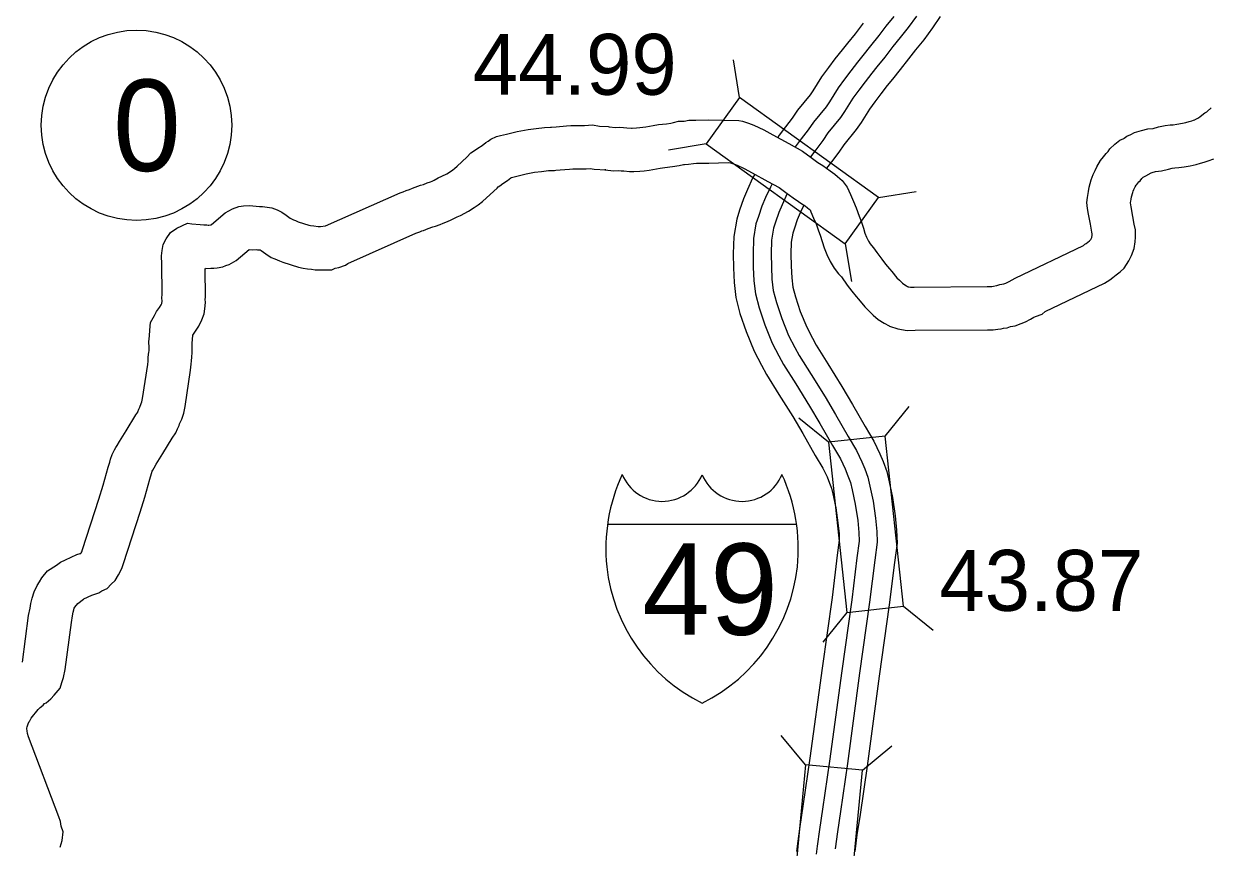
# Model space of a CAD drawing. Extents: x -939622 to -934245, y 1383184 to 1385301.
# Drawn here: x -936357.02 to -936332.35, y 1384807.78 to 1384824.91 of the extents above; entities that cross this region are included whole.
import ezdxf

# ---------------------------------------------------------------- set-up
doc = ezdxf.new("R2010")
doc.units = 0
for name, color, linetype in [('10', 7, 'Continuous'), ('19', 7, 'Continuous'), ('20', 7, 'Continuous'), ('21', 7, 'Continuous'), ('23', 7, 'Continuous'), ('25', 7, 'Continuous'), ('27', 7, 'Continuous')]:
    doc.layers.add(name, color=color, linetype=linetype)

msp = doc.modelspace()

# ---------------------------------------------------------------- linework, layer by layer
at = {"layer": '10'}
for points in [[(-936334.834, 1384820.419), (-936334.834, 1384820.42), (-936334.811, 1384820.463), (-936334.808, 1384820.509), (-936334.807, 1384820.538), (-936334.814, 1384820.572), (-936334.844, 1384820.738), (-936334.883, 1384820.948), (-936334.902, 1384821.064), (-936334.915, 1384821.19), (-936334.904, 1384821.297), (-936334.892, 1384821.375), (-936334.883, 1384821.42), (-936334.869, 1384821.507), (-936334.825, 1384821.66), (-936334.789, 1384821.773), (-936334.747, 1384821.855), (-936334.713, 1384821.931), (-936334.636, 1384822.062), (-936334.572, 1384822.143), (-936334.515, 1384822.208), (-936334.491, 1384822.236), (-936334.477, 1384822.252), (-936334.436, 1384822.307), (-936334.333, 1384822.403), (-936334.228, 1384822.487), (-936334.148, 1384822.526), (-936334.144, 1384822.528), (-936334.084, 1384822.573), (-936334.005, 1384822.605), (-936333.926, 1384822.65), (-936333.781, 1384822.688), (-936333.646, 1384822.721), (-936333.538, 1384822.734), (-936333.429, 1384822.763), (-936333.29, 1384822.792), (-936333.182, 1384822.805), (-936333.122, 1384822.81), (-936333.044, 1384822.824), (-936332.929, 1384822.843), (-936332.862, 1384822.856), (-936332.79, 1384822.878), (-936332.736, 1384822.891), (-936332.7, 1384822.904), (-936332.674, 1384822.913), (-936332.662, 1384822.921), (-936332.599, 1384822.956), (-936332.559, 1384822.982), (-936332.461, 1384823.054), (-936332.423, 1384823.076), (-936332.418, 1384823.081), (-936332.329, 1384823.161)], [(-936346.071, 1384822.758), (-936346.048, 1384822.758), (-936345.952, 1384822.768), (-936345.735, 1384822.786), (-936345.647, 1384822.79), (-936345.518, 1384822.795), (-936345.364, 1384822.794), (-936345.195, 1384822.808), (-936345.05, 1384822.779), (-936344.868, 1384822.769), (-936344.849, 1384822.767), (-936344.716, 1384822.754), (-936344.632, 1384822.755), (-936344.553, 1384822.749), (-936344.48, 1384822.746), (-936344.388, 1384822.737), (-936344.373, 1384822.737), (-936344.283, 1384822.743), (-936344.216, 1384822.749), (-936344.151, 1384822.756), (-936344.09, 1384822.768), (-936343.937, 1384822.791), (-936343.822, 1384822.812), (-936343.655, 1384822.829), (-936343.565, 1384822.844), (-936343.51, 1384822.856)], [(-936343.51, 1384822.856), (-936343.407, 1384822.883), (-936343.291, 1384822.885), (-936343.192, 1384822.904), (-936343.047, 1384822.905), (-936342.79, 1384822.908), (-936342.155, 1384822.899)], [(-936342.155, 1384822.899), (-936342.08, 1384822.88), (-936341.953, 1384822.839), (-936341.842, 1384822.799), (-936341.635, 1384822.702), (-936341.446, 1384822.598), (-936341.114, 1384822.418), (-936340.832, 1384822.261), (-936340.647, 1384822.128), (-936340.509, 1384822.026), (-936340.41, 1384821.959), (-936340.332, 1384821.905), (-936340.252, 1384821.85), (-936340.157, 1384821.779), (-936340.105, 1384821.733), (-936340.008, 1384821.65), (-936339.901, 1384821.508), (-936339.831, 1384821.359), (-936339.772, 1384821.214), (-936339.713, 1384821.079), (-936339.651, 1384820.908), (-936339.613, 1384820.803), (-936339.564, 1384820.655), (-936339.531, 1384820.55), (-936339.501, 1384820.472), (-936339.459, 1384820.388), (-936339.426, 1384820.331), (-936339.397, 1384820.295), (-936339.352, 1384820.246), (-936339.284, 1384820.153)], [(-936354.15, 1384819.908), (-936354.16, 1384820.084), (-936354.148, 1384820.196), (-936354.122, 1384820.317), (-936354.059, 1384820.438), (-936353.97, 1384820.57), (-936353.839, 1384820.66), (-936353.615, 1384820.761), (-936353.53, 1384820.749), (-936353.355, 1384820.736), (-936353.278, 1384820.73), (-936353.215, 1384820.724), (-936353.192, 1384820.721), (-936353.172, 1384820.722), (-936353.142, 1384820.724), (-936353.128, 1384820.725), (-936353.119, 1384820.731), (-936352.833, 1384820.975), (-936352.684, 1384821.057), (-936352.551, 1384821.108), (-936352.451, 1384821.119), (-936352.328, 1384821.128), (-936352.124, 1384821.109), (-936352.058, 1384821.11), (-936351.96, 1384821.095), (-936351.864, 1384821.079), (-936351.751, 1384821.036), (-936351.656, 1384820.989), (-936351.57, 1384820.928), (-936351.483, 1384820.868), (-936351.471, 1384820.859), (-936351.411, 1384820.83), (-936351.376, 1384820.818), (-936351.315, 1384820.791), (-936351.097, 1384820.721), (-936351.064, 1384820.715), (-936350.989, 1384820.703), (-936350.898, 1384820.692), (-936350.883, 1384820.689), (-936350.874, 1384820.689), (-936350.85, 1384820.689), (-936350.746, 1384820.704), (-936349.198, 1384821.392), (-936349.131, 1384821.414), (-936349.073, 1384821.442), (-936349.001, 1384821.463), (-936348.937, 1384821.488), (-936348.773, 1384821.55), (-936348.711, 1384821.563), (-936348.709, 1384821.564), (-936348.637, 1384821.598), (-936348.563, 1384821.622), (-936348.53, 1384821.636), (-936348.492, 1384821.656), (-936348.407, 1384821.703), (-936348.329, 1384821.737), (-936348.225, 1384821.791), (-936348.152, 1384821.838), (-936348.101, 1384821.872), (-936348.068, 1384821.898), (-936348.013, 1384821.949), (-936347.811, 1384822.137), (-936347.728, 1384822.222), (-936347.629, 1384822.284), (-936347.58, 1384822.32), (-936347.493, 1384822.378), (-936347.415, 1384822.439), (-936347.369, 1384822.468), (-936347.312, 1384822.509), (-936347.192, 1384822.562), (-936347.107, 1384822.584), (-936346.983, 1384822.616), (-936346.76, 1384822.667), (-936346.537, 1384822.71), (-936346.371, 1384822.728), (-936346.193, 1384822.753), (-936346.071, 1384822.758)], [(-936339.03, 1384818.624), (-936339.022, 1384818.619), (-936338.845, 1384818.564), (-936338.656, 1384818.526), (-936338.487, 1384818.532), (-936336.98, 1384818.541), (-936336.863, 1384818.543), (-936336.766, 1384818.554), (-936336.698, 1384818.566), (-936336.649, 1384818.575), (-936336.576, 1384818.586), (-936336.505, 1384818.609), (-936336.408, 1384818.627), (-936336.282, 1384818.674), (-936336.191, 1384818.71), (-936336.092, 1384818.763), (-936336.018, 1384818.806), (-936335.987, 1384818.821), (-936335.845, 1384818.87), (-936335.781, 1384818.923), (-936334.55, 1384819.512), (-936334.441, 1384819.582), (-936334.377, 1384819.63), (-936334.308, 1384819.685), (-936334.223, 1384819.75), (-936334.144, 1384819.827), (-936334.042, 1384819.979), (-936334.019, 1384820.035), (-936333.988, 1384820.092), (-936333.931, 1384820.236), (-936333.915, 1384820.371), (-936333.908, 1384820.469), (-936333.905, 1384820.62), (-936333.93, 1384820.742), (-936333.958, 1384820.899), (-936333.996, 1384821.103), (-936334.009, 1384821.183), (-936334.01, 1384821.189), (-936334.005, 1384821.221), (-936333.997, 1384821.26), (-936333.989, 1384821.311), (-936333.964, 1384821.399), (-936333.954, 1384821.43), (-936333.937, 1384821.463), (-936333.914, 1384821.514), (-936333.891, 1384821.552), (-936333.879, 1384821.568), (-936333.835, 1384821.618), (-936333.812, 1384821.645), (-936333.773, 1384821.689), (-936333.761, 1384821.706), (-936333.746, 1384821.72), (-936333.744, 1384821.721), (-936333.694, 1384821.746), (-936333.582, 1384821.81), (-936333.561, 1384821.816), (-936333.487, 1384821.833), (-936333.368, 1384821.847), (-936333.22, 1384821.887), (-936333.145, 1384821.903), (-936333.086, 1384821.91), (-936333.002, 1384821.918), (-936332.895, 1384821.936), (-936332.771, 1384821.957), (-936332.642, 1384821.982), (-936332.552, 1384822.01), (-936332.475, 1384822.028), (-936332.392, 1384822.058), (-936332.28, 1384822.099)], [(-936353.252, 1384819.822), (-936353.237, 1384819.821), (-936353.131, 1384819.822), (-936353.071, 1384819.827), (-936353.002, 1384819.832), (-936352.887, 1384819.854), (-936352.824, 1384819.878), (-936352.751, 1384819.898), (-936352.609, 1384819.983), (-936352.336, 1384820.215), (-936352.26, 1384820.203), (-936352.193, 1384820.211), (-936352.161, 1384820.208), (-936352.119, 1384820.209), (-936352.11, 1384820.208), (-936352.09, 1384820.193), (-936351.989, 1384820.123), (-936351.879, 1384820.05), (-936351.805, 1384820.021), (-936351.755, 1384819.997), (-936351.705, 1384819.98), (-936351.635, 1384819.948), (-936351.311, 1384819.845), (-936351.213, 1384819.828), (-936351.12, 1384819.812), (-936351.038, 1384819.802), (-936350.962, 1384819.788), (-936350.864, 1384819.789), (-936350.801, 1384819.79), (-936350.756, 1384819.79), (-936350.615, 1384819.792), (-936350.546, 1384819.825), (-936350.47, 1384819.841), (-936350.333, 1384819.889), (-936350.285, 1384819.924), (-936348.872, 1384820.552), (-936348.79, 1384820.579), (-936348.748, 1384820.6), (-936348.713, 1384820.61), (-936348.616, 1384820.647), (-936348.518, 1384820.684), (-936348.461, 1384820.696), (-936348.361, 1384820.733), (-936348.302, 1384820.761), (-936348.245, 1384820.78), (-936348.147, 1384820.821), (-936348.066, 1384820.863), (-936348.008, 1384820.895), (-936347.944, 1384820.923), (-936347.774, 1384821.011), (-936347.658, 1384821.086), (-936347.572, 1384821.143), (-936347.481, 1384821.215), (-936347.4, 1384821.291), (-936347.182, 1384821.492), (-936347.158, 1384821.517), (-936347.121, 1384821.54), (-936347.063, 1384821.583), (-936346.966, 1384821.648), (-936346.896, 1384821.702), (-936346.88, 1384821.712), (-936346.769, 1384821.742), (-936346.574, 1384821.786), (-936346.403, 1384821.819), (-936346.259, 1384821.835), (-936346.114, 1384821.856), (-936345.99, 1384821.86), (-936345.96, 1384821.863)], [(-936345.96, 1384821.863), (-936345.871, 1384821.871), (-936345.675, 1384821.888), (-936345.608, 1384821.891), (-936345.504, 1384821.895), (-936345.329, 1384821.894), (-936345.246, 1384821.901), (-936345.164, 1384821.885), (-936344.921, 1384821.87), (-936344.94, 1384821.872), (-936344.756, 1384821.853), (-936344.66, 1384821.854), (-936344.602, 1384821.85), (-936344.543, 1384821.848), (-936344.43, 1384821.836), (-936344.338, 1384821.837), (-936344.213, 1384821.846), (-936344.124, 1384821.853), (-936344.016, 1384821.866), (-936343.94, 1384821.88), (-936343.789, 1384821.903), (-936343.694, 1384821.92), (-936343.533, 1384821.937), (-936343.396, 1384821.96), (-936343.302, 1384821.98), (-936343.285, 1384821.985), (-936343.199, 1384821.986), (-936343.1, 1384822.005), (-936343.036, 1384822.006), (-936342.779, 1384822.009), (-936342.375, 1384822.026)], [(-936342.375, 1384822.026), (-936342.327, 1384822.014), (-936342.244, 1384821.987), (-936342.187, 1384821.967), (-936342.043, 1384821.899), (-936341.877, 1384821.808), (-936341.548, 1384821.629), (-936341.316, 1384821.501), (-936341.178, 1384821.401), (-936341.027, 1384821.29), (-936340.916, 1384821.215), (-936340.843, 1384821.165), (-936340.778, 1384821.12), (-936340.723, 1384821.078), (-936340.694, 1384821.053), (-936340.674, 1384821.036), (-936340.655, 1384820.996), (-936340.601, 1384820.864), (-936340.549, 1384820.745), (-936340.498, 1384820.602), (-936340.464, 1384820.51), (-936340.421, 1384820.378), (-936340.38, 1384820.25), (-936340.324, 1384820.107), (-936340.253, 1384819.964), (-936340.173, 1384819.824), (-936340.081, 1384819.708), (-936340.022, 1384819.645), (-936339.902, 1384819.474)], [(-936338.631, 1384819.44), (-936338.622, 1384819.437), (-936338.583, 1384819.429), (-936338.506, 1384819.432), (-936336.988, 1384819.441), (-936336.919, 1384819.442), (-936336.896, 1384819.445), (-936336.857, 1384819.452), (-936336.798, 1384819.462), (-936336.788, 1384819.464), (-936336.728, 1384819.484), (-936336.646, 1384819.499), (-936336.605, 1384819.514), (-936336.571, 1384819.527), (-936336.534, 1384819.547), (-936336.411, 1384819.62), (-936334.989, 1384820.299), (-936334.956, 1384820.321), (-936334.93, 1384820.34), (-936334.863, 1384820.394), (-936334.832, 1384820.418)], [(-936339.284, 1384820.153), (-936339.181, 1384820.013), (-936339.102, 1384819.91), (-936339.018, 1384819.811), (-936338.971, 1384819.753), (-936338.867, 1384819.627), (-936338.814, 1384819.573), (-936338.752, 1384819.515), (-936338.723, 1384819.489), (-936338.669, 1384819.457), (-936338.65, 1384819.446), (-936338.631, 1384819.44)], [(-936357.047, 1384811.625), (-936356.922, 1384812.598), (-936356.892, 1384812.755), (-936356.877, 1384812.846), (-936356.85, 1384812.96), (-936356.808, 1384813.091), (-936356.744, 1384813.22), (-936356.696, 1384813.299), (-936356.646, 1384813.381), (-936356.53, 1384813.528), (-936356.344, 1384813.643), (-936356.262, 1384813.708), (-936356.157, 1384813.759), (-936355.919, 1384813.867), (-936355.852, 1384813.887), (-936355.838, 1384813.892), (-936355.829, 1384813.901), (-936355.817, 1384813.926), (-936355.801, 1384813.97), (-936355.459, 1384815.019), (-936355.37, 1384815.313), (-936355.266, 1384815.687), (-936355.234, 1384815.791), (-936355.219, 1384815.853), (-936355.188, 1384815.95), (-936355.137, 1384816.049), (-936355.108, 1384816.095), (-936355.084, 1384816.136), (-936355.034, 1384816.216), (-936354.897, 1384816.442), (-936354.693, 1384816.772), (-936354.653, 1384816.832), (-936354.651, 1384816.838), (-936354.628, 1384816.893), (-936354.612, 1384816.932), (-936354.58, 1384817.007), (-936354.568, 1384817.043), (-936354.553, 1384817.111), (-936354.446, 1384817.823), (-936354.438, 1384817.888), (-936354.436, 1384817.973), (-936354.42, 1384818.08), (-936354.418, 1384818.104), (-936354.419, 1384818.178), (-936354.421, 1384818.294), (-936354.411, 1384818.416), (-936354.401, 1384818.533), (-936354.389, 1384818.694), (-936354.308, 1384818.843), (-936354.26, 1384818.923), (-936354.199, 1384819.01), (-936354.168, 1384819.059), (-936354.154, 1384819.088), (-936354.151, 1384819.097), (-936354.148, 1384819.131), (-936354.152, 1384819.215), (-936354.145, 1384819.267), (-936354.151, 1384819.929)], [(-936356.264, 1384807.782), (-936356.227, 1384807.92), (-936356.207, 1384808.097), (-936356.244, 1384808.216), (-936356.259, 1384808.311), (-936356.297, 1384808.41), (-936356.927, 1384810.074), (-936356.946, 1384810.145), (-936356.955, 1384810.199), (-936356.962, 1384810.238), (-936356.96, 1384810.256), (-936356.955, 1384810.281), (-936356.945, 1384810.307), (-936356.929, 1384810.346), (-936356.909, 1384810.394), (-936356.899, 1384810.41), (-936356.87, 1384810.462), (-936356.721, 1384810.642), (-936356.681, 1384810.686), (-936356.622, 1384810.732), (-936356.59, 1384810.765), (-936356.559, 1384810.785), (-936356.46, 1384810.867), (-936356.388, 1384810.942), (-936356.269, 1384811.09), (-936356.229, 1384811.206), (-936356.194, 1384811.308), (-936356.159, 1384811.477), (-936356.033, 1384812.456), (-936356.007, 1384812.594), (-936355.995, 1384812.666), (-936355.982, 1384812.72), (-936355.972, 1384812.751), (-936355.962, 1384812.77), (-936355.899, 1384812.848), (-936355.78, 1384812.941), (-936355.772, 1384812.945), (-936355.605, 1384813.022), (-936355.565, 1384813.033), (-936355.463, 1384813.072), (-936355.397, 1384813.109), (-936355.287, 1384813.161), (-936355.209, 1384813.248), (-936355.121, 1384813.329), (-936355.05, 1384813.443), (-936354.986, 1384813.577), (-936354.949, 1384813.678), (-936354.6, 1384814.749), (-936354.505, 1384815.063), (-936354.402, 1384815.434), (-936354.365, 1384815.554), (-936354.353, 1384815.604), (-936354.341, 1384815.624), (-936354.312, 1384815.673), (-936354.268, 1384815.744), (-936354.129, 1384815.972), (-936353.934, 1384816.288), (-936353.862, 1384816.397), (-936353.824, 1384816.481), (-936353.795, 1384816.553), (-936353.782, 1384816.586), (-936353.738, 1384816.686), (-936353.698, 1384816.807), (-936353.668, 1384816.949), (-936353.554, 1384817.704), (-936353.54, 1384817.825), (-936353.538, 1384817.895), (-936353.526, 1384817.975), (-936353.518, 1384818.071), (-936353.519, 1384818.189), (-936353.52, 1384818.265), (-936353.514, 1384818.341), (-936353.506, 1384818.429), (-936353.506, 1384818.43), (-936353.449, 1384818.512), (-936353.38, 1384818.621), (-936353.318, 1384818.748), (-936353.275, 1384818.877), (-936353.258, 1384818.976), (-936353.246, 1384819.114), (-936353.249, 1384819.18), (-936353.245, 1384819.212), (-936353.25, 1384819.821)], [(-936339.902, 1384819.474), (-936339.804, 1384819.346), (-936339.712, 1384819.237), (-936339.668, 1384819.182), (-936339.535, 1384819.023), (-936339.443, 1384818.929), (-936339.359, 1384818.85), (-936339.255, 1384818.758), (-936339.129, 1384818.684), (-936339.03, 1384818.624)]]:
    msp.add_lwpolyline(points, dxfattribs=at)
at = {"layer": '19'}
for points in [[(-936338.933, 1384825.058), (-936339.094, 1384824.857), (-936339.245, 1384824.667), (-936339.414, 1384824.448), (-936339.574, 1384824.249), (-936339.684, 1384824.112), (-936339.828, 1384823.93), (-936339.958, 1384823.754), (-936340.09, 1384823.574), (-936340.27, 1384823.287), (-936340.341, 1384823.183), (-936340.601, 1384822.863), (-936340.713, 1384822.703), (-936340.855, 1384822.517), (-936340.984, 1384822.346)], [(-936338.461, 1384825.066), (-936338.636, 1384824.83), (-936338.8, 1384824.623), (-936338.95, 1384824.435), (-936339.12, 1384824.216), (-936339.282, 1384824.014), (-936339.39, 1384823.879), (-936339.529, 1384823.702), (-936339.656, 1384823.531), (-936339.78, 1384823.363), (-936339.956, 1384823.081), (-936340.041, 1384822.958), (-936340.301, 1384822.638), (-936340.41, 1384822.481), (-936340.556, 1384822.29), (-936340.667, 1384822.142)], [(-936337.965, 1384825.062), (-936338.124, 1384824.828), (-936338.309, 1384824.578), (-936338.478, 1384824.366), (-936338.626, 1384824.18), (-936338.796, 1384823.961), (-936338.96, 1384823.756), (-936339.067, 1384823.622), (-936339.202, 1384823.452), (-936339.324, 1384823.286), (-936339.438, 1384823.131), (-936339.612, 1384822.854), (-936339.711, 1384822.711), (-936339.971, 1384822.389), (-936340.077, 1384822.238), (-936340.228, 1384822.04), (-936340.33, 1384821.904)], [(-936339.569, 1384824.922), (-936339.738, 1384824.703), (-936339.896, 1384824.507), (-936340.006, 1384824.369), (-936340.156, 1384824.18), (-936340.289, 1384823.999), (-936340.432, 1384823.806), (-936340.614, 1384823.514), (-936340.671, 1384823.431), (-936340.931, 1384823.111), (-936341.046, 1384822.946), (-936341.183, 1384822.766), (-936341.314, 1384822.594), (-936341.345, 1384822.544)], [(-936341.823, 1384821.779), (-936341.868, 1384821.698), (-936341.975, 1384821.459), (-936342.059, 1384821.265), (-936342.138, 1384821.032), (-936342.198, 1384820.844), (-936342.261, 1384820.485), (-936342.27, 1384820.125), (-936342.265, 1384819.83), (-936342.251, 1384819.529), (-936342.214, 1384819.213), (-936342.13, 1384818.884), (-936342.001, 1384818.504), (-936341.834, 1384818.095), (-936341.686, 1384817.806), (-936341.581, 1384817.613), (-936341.321, 1384817.198), (-936341.034, 1384816.739), (-936340.824, 1384816.386), (-936340.564, 1384815.928), (-936340.405, 1384815.662), (-936340.32, 1384815.482), (-936340.268, 1384815.353), (-936340.226, 1384815.248), (-936340.2, 1384815.127), (-936340.138, 1384814.84), (-936340.092, 1384814.525), (-936340.07, 1384814.298), (-936340.066, 1384814.164)], [(-936341.461, 1384821.581), (-936341.498, 1384821.513), (-936341.597, 1384821.292), (-936341.674, 1384821.116), (-936341.746, 1384820.903), (-936341.797, 1384820.745), (-936341.85, 1384820.445), (-936341.857, 1384820.123), (-936341.853, 1384819.843), (-936341.839, 1384819.563), (-936341.807, 1384819.288), (-936341.734, 1384819.001), (-936341.614, 1384818.649), (-936341.459, 1384818.268), (-936341.321, 1384817.999), (-936341.224, 1384817.822), (-936340.971, 1384817.416), (-936340.682, 1384816.954), (-936340.468, 1384816.593), (-936340.207, 1384816.136), (-936340.041, 1384815.856), (-936339.943, 1384815.648), (-936339.885, 1384815.507), (-936339.83, 1384815.368), (-936339.797, 1384815.214), (-936339.732, 1384814.913), (-936339.682, 1384814.575), (-936339.658, 1384814.324), (-936339.652, 1384814.143)], [(-936341.148, 1384821.379), (-936341.254, 1384821.141), (-936341.324, 1384820.981), (-936341.39, 1384820.785), (-936341.432, 1384820.654), (-936341.475, 1384820.408), (-936341.482, 1384820.121), (-936341.478, 1384819.855), (-936341.465, 1384819.594), (-936341.438, 1384819.357), (-936341.374, 1384819.108), (-936341.263, 1384818.78), (-936341.118, 1384818.424), (-936340.99, 1384818.174), (-936340.901, 1384818.011), (-936340.653, 1384817.615), (-936340.361, 1384817.149), (-936340.143, 1384816.782), (-936339.883, 1384816.325), (-936339.709, 1384816.032), (-936339.599, 1384815.799), (-936339.537, 1384815.647), (-936339.47, 1384815.477), (-936339.43, 1384815.292), (-936339.363, 1384814.98), (-936339.31, 1384814.621), (-936339.284, 1384814.348), (-936339.277, 1384814.124)], [(-936340.804, 1384821.138), (-936340.876, 1384820.975), (-936340.938, 1384820.832), (-936340.999, 1384820.655), (-936341.031, 1384820.555), (-936341.064, 1384820.367), (-936341.07, 1384820.12), (-936341.066, 1384819.869), (-936341.054, 1384819.627), (-936341.031, 1384819.432), (-936340.979, 1384819.226), (-936340.876, 1384818.924), (-936340.742, 1384818.596), (-936340.625, 1384818.367), (-936340.545, 1384818.22), (-936340.303, 1384817.834), (-936340.009, 1384817.363), (-936339.787, 1384816.989), (-936339.527, 1384816.532), (-936339.344, 1384816.226), (-936339.221, 1384815.965), (-936339.154, 1384815.801), (-936339.073, 1384815.596), (-936339.027, 1384815.379), (-936338.957, 1384815.054), (-936338.9, 1384814.67), (-936338.872, 1384814.374), (-936338.863, 1384814.104)], [(-936340.066, 1384814.164), (-936340.108, 1384813.852), (-936340.215, 1384812.976), (-936340.423, 1384811.504), (-936340.676, 1384809.628), (-936340.821, 1384808.633), (-936340.885, 1384808.208), (-936340.933, 1384807.854), (-936340.956, 1384807.692)], [(-936339.652, 1384814.143), (-936339.698, 1384813.799), (-936339.806, 1384812.922), (-936340.014, 1384811.447), (-936340.268, 1384809.571), (-936340.413, 1384808.572), (-936340.476, 1384808.15), (-936340.524, 1384807.798), (-936340.547, 1384807.634)], [(-936339.277, 1384814.124), (-936339.327, 1384813.752), (-936339.435, 1384812.873), (-936339.643, 1384811.396), (-936339.896, 1384809.519), (-936340.042, 1384808.518), (-936340.105, 1384808.097), (-936340.153, 1384807.746)], [(-936338.863, 1384814.104), (-936338.917, 1384813.699), (-936339.026, 1384812.819), (-936339.234, 1384811.34), (-936339.488, 1384809.462), (-936339.634, 1384808.457), (-936339.697, 1384808.038), (-936339.744, 1384807.689)]]:
    msp.add_lwpolyline(points, dxfattribs=at)
at = {"layer": '20'}
for p, q in [((-936342.141, 1384823.375), (-936342.268, 1384824.157)), ((-936342.834, 1384822.411), (-936343.616, 1384822.283)), ((-936339.247, 1384821.295), (-936338.465, 1384821.423)), ((-936339.941, 1384820.33), (-936339.813, 1384819.549)), ((-936339.109, 1384816.333), (-936338.612, 1384816.95)), ((-936340.29, 1384816.206), (-936340.907, 1384816.703)), ((-936338.727, 1384812.79), (-936338.111, 1384812.293)), ((-936339.909, 1384812.663), (-936340.405, 1384812.046)), ((-936340.768, 1384809.492), (-936341.273, 1384810.103)), ((-936339.585, 1384809.381), (-936338.975, 1384809.886))]:
    msp.add_line(p, q, dxfattribs=at)
for points in [[(-936339.247, 1384821.295), (-936342.141, 1384823.375), (-936342.834, 1384822.411), (-936339.941, 1384820.33)], [(-936338.727, 1384812.79), (-936339.109, 1384816.333), (-936340.29, 1384816.206), (-936339.909, 1384812.663)], [(-936339.92, 1384805.833), (-936339.585, 1384809.381), (-936340.768, 1384809.492), (-936341.103, 1384805.944)]]:
    msp.add_lwpolyline(points, close=True, dxfattribs=at)
at = {"layer": '23'}
msp.add_line((-936344.885, 1384814.499), (-936340.952, 1384814.499), dxfattribs=at)
for centre, radius, start, end in [((-936341.23, 1384813.987), 3.69, 155.2204, 185.7928), ((-936343.748, 1384815.873), 0.899, 202.1459, 337.3414), ((-936342.089, 1384815.873), 0.899, 202.6586, 337.8541), ((-936344.607, 1384813.987), 3.69, 354.2072, 24.7796), ((-936341.298, 1384814.018), 3.626, 186.3923, 243.4571), ((-936344.539, 1384814.018), 3.626, 296.5429, 353.6077)]:
    msp.add_arc(centre, radius, start, end, dxfattribs=at)
at = {"layer": '27'}
msp.add_circle((-936354.678, 1384822.797), 1.98, dxfattribs=at)

# ---------------------------------------------------------------- texts
at = {"layer": '21'}
msp.add_text('49', height=1.9008, dxfattribs=at).set_placement((-936344.166, 1384812.197))
at = {"layer": '25'}
for s, p in [('44.99', (-936347.686, 1384823.432)), ('43.87', (-936337.984, 1384812.696))]:
    msp.add_text(s, height=1.2672, dxfattribs=at).set_placement(p)
at = {"layer": '27'}
msp.add_text('0', height=1.901, rotation=359.9, dxfattribs=at).set_placement((-936355.17, 1384821.848))

doc.saveas('drawing.dxf')
